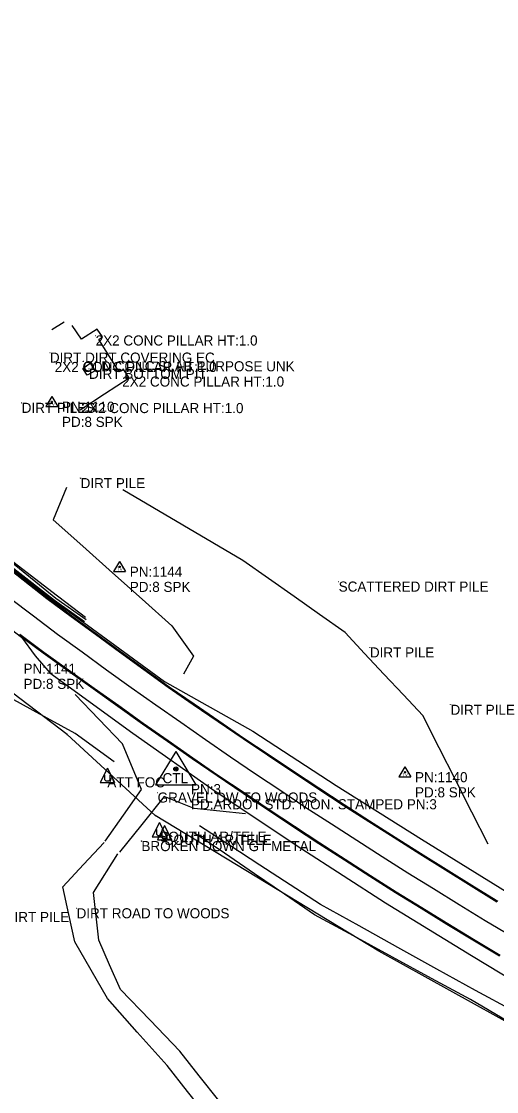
# Model space of a CAD drawing. Extents: x 878399 to 889864, y 1564003 to 1567413.
# Drawn here: x 885279 to 885515, y 1564809 to 1565340 of the extents above; entities that cross this region are included whole.
import ezdxf

# ---------------------------------------------------------------- set-up
doc = ezdxf.new("R2010")
doc.units = 0
for name, color, linetype in [('S_DITCHLINE', 7, 'Continuous'), ('S_DRIVEWAY', 7, 'Continuous'), ('S_EDGE_CONCRETE', 7, 'Continuous'), ('S_EDGE_PAVEMENT', 7, 'Continuous'), ('S_FIBER_OPTIC_CABLE', 7, 'Continuous'), ('S_GRAVEL_ROAD', 7, 'Continuous'), ('S_MSC_PT_SYM', 7, 'Continuous'), ('S_PAVEMENT_CROWN', 7, 'Continuous'), ('S_PRIMARY_CTL', 7, 'Continuous'), ('S_PRIMARY_CTL_ANNOT', 7, 'Continuous'), ('S_SECONDARY_CTL', 7, 'Continuous'), ('S_SECONDARY_CTL_ANNOT', 7, 'Continuous'), ('S_SHOULDER', 7, 'Continuous'), ('S_SURVEY_TEXT_ANNOT', 7, 'Continuous'), ('S_TRAILS', 7, 'Continuous'), ('S_UTILITY_POLE', 7, 'Continuous'), ('S_UTILITY_POLE_ANNOT', 7, 'Continuous'), ('S_UTL_PT_SYM', 7, 'Continuous')]:
    doc.layers.add(name, color=color, linetype=linetype)

msp = doc.modelspace()

# ---------------------------------------------------------------- linework, layer by layer
at = {"layer": 'S_DITCHLINE'}
for points in [[(885310.72, 1565044.3), (885294.14, 1565056.98), (885277.55, 1565069.67), (885260.97, 1565082.35), (885244.38, 1565095.03), (885226.71, 1565109.43), (885209.03, 1565123.82), (885191.36, 1565138.22), (885173.68, 1565152.61), (885155.49, 1565168.05), (885137.3, 1565183.48), (885119.12, 1565198.92), (885100.93, 1565214.35), (885083.52, 1565229.28), (885066.12, 1565244.2), (885048.72, 1565259.13), (885031.31, 1565274.06), (885014.49, 1565288.54), (884997.67, 1565303.02), (884980.86, 1565317.5), (884964.04, 1565331.98), (884961.88, 1565334.22), (884945.54, 1565347.97)], [(885324.96, 1564972.8), (885305.68, 1564986.74), (885284.83, 1564998.14), (885263.97, 1565009.54)], [(885523.05, 1564849.11), (885504.1, 1564859.3), (885484.87, 1564869.98), (885465.64, 1564880.65), (885446.41, 1564891.33), (885427.18, 1564902.01), (885412.2, 1564911.77), (885397.23, 1564921.52), (885382.25, 1564931.27), (885367.27, 1564941.03)], [(885520.12, 1564844.02), (885501.51, 1564854.81), (885482.2, 1564865.34), (885462.88, 1564875.86), (885443.57, 1564886.39), (885424.25, 1564896.92), (885409.36, 1564907.08), (885394.48, 1564917.24), (885379.59, 1564927.4), (885364.7, 1564937.57)]]:
    msp.add_lwpolyline(points, dxfattribs=at)
at = {"layer": 'S_DRIVEWAY'}
for points in [[(885320.58, 1564933.43), (885329.54, 1564946.24), (885338.49, 1564959.06), (885329.06, 1564981.63), (885317.32, 1564993.83), (885305.58, 1565006.04)], [(885390.06, 1564947), (885377.35, 1564948.3), (885364.65, 1564949.59), (885349.83, 1564955.51), (885338.76, 1564941.71), (885327.69, 1564927.92)]]:
    msp.add_lwpolyline(points, dxfattribs=at)
at = {"layer": 'S_EDGE_CONCRETE'}
for points in [[(884706.6, 1565551.45), (884725.44, 1565537.13), (884744.17, 1565521.12), (884782.46, 1565488.91), (884820.33, 1565456.29), (884857.4, 1565422.83), (884893.19, 1565391.5), (884931.44, 1565358.94), (884969.96, 1565327.51), (885007.93, 1565294.95), (885045.65, 1565262.19), (885083.76, 1565229.98), (885121.86, 1565197.67), (885159.74, 1565165.3), (885198.19, 1565133.4), (885236.59, 1565102.25), (885296.12, 1565053.84), (885311.12, 1565043.35)], [(884705.4, 1565550.04), (884723.26, 1565534.58), (884742.1, 1565518.69), (884780.16, 1565486.23), (884818.14, 1565453.73), (884855.98, 1565421.17), (884892.08, 1565390.2), (884930.32, 1565357.68), (884968.08, 1565325.3), (885005.99, 1565292.69), (885044.06, 1565260.33), (885082.07, 1565227.99), (885120, 1565195.47), (885157.99, 1565163.2), (885196.4, 1565131.24), (885234.81, 1565099.94), (885295.36, 1565052.86), (885310.26, 1565042.23)], [(885300.18, 1565190.78), (885293.99, 1565186.85)], [(885308.09, 1565147.19), (885320.22, 1565155.16), (885332.35, 1565163.12), (885329.79, 1565167.13), (885327.42, 1565166.07), (885317.29, 1565182.15), (885319.12, 1565183.47), (885316.62, 1565187.29), (885308.77, 1565182.26), (885304.13, 1565189.13)]]:
    msp.add_lwpolyline(points, dxfattribs=at)
msp.add_lwpolyline([(885311.59, 1565164.36), (885309.49, 1565167.78), (885313.01, 1565170.34), (885315.49, 1565166.6)], close=True, dxfattribs=at)
at = {"layer": 'S_EDGE_PAVEMENT'}
for points in [[(885267.94, 1565072.17), (885279.79, 1565062.98), (885291.64, 1565053.78), (885303.66, 1565044.82), (885315.76, 1565035.95), (885327.54, 1565027.32), (885339.64, 1565018.45), (885351.8, 1565009.67), (885364.17, 1565001.19), (885376.54, 1564992.7), (885388.91, 1564984.21), (885400.99, 1564976.14), (885413.48, 1564967.83), (885425.97, 1564959.51), (885425.97, 1564959.51), (885425.97, 1564959.51), (885438.54, 1564951.32), (885451.17, 1564943.22), (885463.8, 1564935.13), (885463.8, 1564935.13), (885476.45, 1564927.08), (885489.2, 1564919.17), (885501.96, 1564911.27), (885514.71, 1564903.36)], [(885268.33, 1565072.47), (885280.18, 1565063.28), (885292.03, 1565054.09), (885304.05, 1565045.13), (885316.14, 1565036.25), (885327.93, 1565027.62), (885340.03, 1565018.76), (885352.19, 1565009.98), (885364.55, 1565001.49), (885376.92, 1564993.01), (885389.29, 1564984.52), (885401.37, 1564976.45), (885413.86, 1564968.13), (885426.35, 1564959.82), (885426.35, 1564959.82), (885426.35, 1564959.82), (885438.92, 1564951.63), (885451.55, 1564943.53), (885464.18, 1564935.44), (885464.18, 1564935.44), (885476.83, 1564927.39), (885489.58, 1564919.48), (885502.33, 1564911.58), (885515.08, 1564903.67)], [(885277.76, 1565035.77), (885289.77, 1565026.8), (885301.96, 1565018.04), (885314.61, 1565009.01), (885326.82, 1565000.29), (885339.03, 1564991.58), (885351.34, 1564983.01), (885363.65, 1564974.45), (885375.97, 1564965.88), (885388.95, 1564957.15), (885401.44, 1564948.84), (885401.44, 1564948.84), (885401.44, 1564948.84), (885413.93, 1564940.53), (885426.48, 1564932.3), (885439.1, 1564924.19), (885451.72, 1564916.08), (885464.35, 1564907.99), (885477.14, 1564900.15), (885477.14, 1564900.15), (885489.93, 1564892.31), (885502.72, 1564884.47), (885516, 1564876.5)], [(885278.15, 1565036.08), (885290.16, 1565027.1), (885302.35, 1565018.35), (885315, 1565009.31), (885327.2, 1565000.59), (885339.42, 1564991.89), (885351.73, 1564983.32), (885364.04, 1564974.75), (885376.35, 1564966.19), (885389.33, 1564957.46), (885401.82, 1564949.15), (885401.82, 1564949.15), (885401.82, 1564949.15), (885414.32, 1564940.84), (885426.86, 1564932.61), (885439.48, 1564924.5), (885452.1, 1564916.39), (885464.73, 1564908.3), (885477.52, 1564900.46), (885477.52, 1564900.46), (885490.31, 1564892.62), (885503.1, 1564884.78), (885516.37, 1564876.81)]]:
    msp.add_lwpolyline(points, dxfattribs=at)
at = {"layer": 'S_FIBER_OPTIC_CABLE'}
for p, q in [((885301.6, 1564986.24), (885250.1, 1565025.48)), ((885345.35, 1564946.19), (885301.6, 1564986.24)), ((885456.16, 1564878.83), (885345.35, 1564946.19)), ((885547.89, 1564828.01), (885456.16, 1564878.83))]:
    msp.add_line(p, q, dxfattribs=at)
at = {"layer": 'S_GRAVEL_ROAD'}
for points in [[(885301.36, 1565108.82), (885294.78, 1565092.74), (885309.46, 1565079.6), (885324.13, 1565066.46), (885338.8, 1565053.32), (885353.48, 1565040.18), (885364.23, 1565025.11), (885359.33, 1565016.16)], [(885510.35, 1564931.82), (885502.25, 1564947.77), (885494.14, 1564963.73), (885486.04, 1564979.68), (885477.93, 1564995.63), (885468.3, 1565005.92), (885458.67, 1565016.22), (885449.05, 1565026.51), (885439.42, 1565036.81), (885426.77, 1565045.76), (885414.12, 1565054.71), (885401.47, 1565063.67), (885388.81, 1565072.62), (885373.94, 1565081.37), (885359.06, 1565090.12), (885344.18, 1565098.86), (885329.3, 1565107.61)]]:
    msp.add_lwpolyline(points, dxfattribs=at)
at = {"layer": 'S_MSC_PT_SYM'}
for points in [[(885315.78, 1565184.13), (885315.78, 1565184.18), (885315.78, 1565184.13), (885315.73, 1565184.13), (885315.78, 1565184.13), (885315.78, 1565184.08), (885315.78, 1565184.13), (885315.83, 1565184.13)], [(885293.11, 1565175.64), (885293.11, 1565175.69), (885293.11, 1565175.64), (885293.06, 1565175.64), (885293.11, 1565175.64), (885293.11, 1565175.59), (885293.11, 1565175.64), (885293.16, 1565175.64)], [(885295.49, 1565170.99), (885295.49, 1565171.04), (885295.49, 1565170.99), (885295.44, 1565170.99), (885295.49, 1565170.99), (885295.49, 1565170.94), (885295.49, 1565170.99), (885295.54, 1565170.99)], [(885309.66, 1565171.34), (885309.66, 1565171.39), (885309.66, 1565171.34), (885309.61, 1565171.34), (885309.66, 1565171.34), (885309.66, 1565171.29), (885309.66, 1565171.34), (885309.71, 1565171.34)], [(885312.51, 1565167.6), (885312.51, 1565167.65), (885312.51, 1565167.6), (885312.46, 1565167.6), (885312.51, 1565167.6), (885312.51, 1565167.55), (885312.51, 1565167.6), (885312.56, 1565167.6)], [(885328.95, 1565163.76), (885328.95, 1565163.81), (885328.95, 1565163.76), (885328.9, 1565163.76), (885328.95, 1565163.76), (885328.95, 1565163.71), (885328.95, 1565163.76), (885329, 1565163.76)], [(885279.13, 1565150.74), (885279.13, 1565150.79), (885279.13, 1565150.74), (885279.08, 1565150.74), (885279.13, 1565150.74), (885279.13, 1565150.69), (885279.13, 1565150.74), (885279.18, 1565150.74)], [(885308.79, 1565150.62), (885308.79, 1565150.67), (885308.79, 1565150.62), (885308.74, 1565150.62), (885308.79, 1565150.62), (885308.79, 1565150.57), (885308.79, 1565150.62), (885308.84, 1565150.62)], [(885308.34, 1565113.41), (885308.34, 1565113.46), (885308.34, 1565113.41), (885308.29, 1565113.41), (885308.34, 1565113.41), (885308.34, 1565113.36), (885308.34, 1565113.41), (885308.39, 1565113.41)], [(885436.24, 1565062.11), (885436.24, 1565062.16), (885436.24, 1565062.11), (885436.19, 1565062.11), (885436.24, 1565062.11), (885436.24, 1565062.06), (885436.24, 1565062.11), (885436.29, 1565062.11)], [(885451.72, 1565029.46), (885451.72, 1565029.51), (885451.72, 1565029.46), (885451.67, 1565029.46), (885451.72, 1565029.46), (885451.72, 1565029.41), (885451.72, 1565029.46), (885451.77, 1565029.46)], [(885491.67, 1565001.03), (885491.67, 1565001.08), (885491.67, 1565001.03), (885491.62, 1565001.03), (885491.67, 1565001.03), (885491.67, 1565000.98), (885491.67, 1565001.03), (885491.72, 1565001.03)], [(885346.5, 1564957.53), (885346.5, 1564957.58), (885346.5, 1564957.53), (885346.45, 1564957.53), (885346.5, 1564957.53), (885346.5, 1564957.48), (885346.5, 1564957.53), (885346.55, 1564957.53)], [(885338.48, 1564933.44), (885338.48, 1564933.49), (885338.48, 1564933.44), (885338.43, 1564933.44), (885338.48, 1564933.44), (885338.48, 1564933.39), (885338.48, 1564933.44), (885338.53, 1564933.44)], [(885306.33, 1564900.15), (885306.33, 1564900.2), (885306.33, 1564900.15), (885306.28, 1564900.15), (885306.33, 1564900.15), (885306.33, 1564900.1), (885306.33, 1564900.15), (885306.38, 1564900.15)]]:
    msp.add_lwpolyline(points, dxfattribs=at)
at = {"layer": 'S_PAVEMENT_CROWN'}
msp.add_lwpolyline([(885272.99, 1565054.15), (885284.94, 1565045.08), (885296.92, 1565036.06), (885309.05, 1565027.24), (885321.24, 1565018.39), (885333.37, 1565009.57), (885345.64, 1565000.94), (885357.94, 1564992.36), (885370.24, 1564983.77), (885382.61, 1564975.28), (885395.1, 1564966.85), (885407.54, 1564958.46), (885420.01, 1564950.12), (885432.62, 1564941.99), (885445.23, 1564933.86), (885457.83, 1564925.73), (885470.55, 1564917.77), (885483.29, 1564909.85), (885496.03, 1564901.93), (885508.85, 1564894.12), (885521.79, 1564886.41)], dxfattribs=at)
at = {"layer": 'S_PRIMARY_CTL'}
for p, q in [((885355.55, 1564977.89), (885345.51, 1564961.38)), ((885355.55, 1564977.89), (885365.37, 1564961.38)), ((885345.51, 1564961.38), (885365.37, 1564961.38))]:
    msp.add_line(p, q, dxfattribs=at)
for radius in [1.04, 0.609, 0.344]:
    msp.add_circle((885355.55, 1564969.19), radius, dxfattribs=at)
at = {"layer": 'S_SECONDARY_CTL'}
for p, q in [((885294.09, 1565153.89), (885291.08, 1565148.93)), ((885294.09, 1565153.89), (885297.04, 1565148.93)), ((885291.08, 1565148.93), (885297.04, 1565148.93)), ((885327.69, 1565072.07), (885324.68, 1565067.12)), ((885327.69, 1565072.07), (885330.64, 1565067.12)), ((885324.68, 1565067.12), (885330.64, 1565067.12)), ((885469.09, 1564970.22), (885466.08, 1564965.26)), ((885469.09, 1564970.22), (885472.04, 1564965.26)), ((885466.08, 1564965.26), (885472.04, 1564965.26))]:
    msp.add_line(p, q, dxfattribs=at)
for centre, radius in [((885294.09, 1565151.27), 0.311), ((885294.09, 1565151.27), 0.183), ((885294.09, 1565151.27), 0.103), ((885327.69, 1565069.46), 0.311), ((885327.69, 1565069.46), 0.183), ((885327.69, 1565069.46), 0.103), ((885469.09, 1564967.61), 0.311), ((885469.09, 1564967.61), 0.183), ((885469.09, 1564967.61), 0.103)]:
    msp.add_circle(centre, radius, dxfattribs=at)
at = {"layer": 'S_SHOULDER'}
for points in [[(884891.75, 1565389.81), (884929.91, 1565357.22), (884967.7, 1565324.86), (885005.68, 1565292.33), (885043.8, 1565260.03), (885081.58, 1565227.41), (885119.6, 1565195.01), (885157.6, 1565162.73), (885196.01, 1565130.77), (885234.52, 1565099.56), (885295.12, 1565052.54), (885309.99, 1565041.88), (885349.92, 1565012.53), (885393.73, 1564987.91), (885434.98, 1564961), (885477.34, 1564934.42), (885519.82, 1564908.04)], [(884883.27, 1565365.1), (884921.11, 1565332.91), (884959.44, 1565300.44), (884997.33, 1565267.94), (885035.39, 1565235.57), (885073.41, 1565203.07), (885111.37, 1565170.59), (885149.81, 1565138.45), (885188.01, 1565106.23), (885227.26, 1565074.48), (885266.77, 1565043.86), (885279.08, 1565034.55), (885285.74, 1565025.23), (885293.12, 1565016.93), (885334.15, 1564986.97), (885375, 1564958.16), (885417.46, 1564929.91), (885459.52, 1564902.88), (885502.12, 1564876.69), (885545.5, 1564850.36)]]:
    msp.add_lwpolyline(points, dxfattribs=at)
at = {"layer": 'S_TRAILS'}
for points in [[(885416.6, 1564707.68), (885409.49, 1564727.82), (885402.37, 1564747.96), (885394.65, 1564760.08), (885386.93, 1564772.21), (885379.21, 1564784.33), (885371.49, 1564796.45), (885361.33, 1564809.27), (885351.18, 1564822.09), (885336.4, 1564838.75), (885321.63, 1564855.4), (885313.57, 1564869.43), (885305.5, 1564883.46), (885302.5, 1564897.11), (885299.51, 1564910.76), (885309.8, 1564921.76), (885320.09, 1564932.75)], [(885424.31, 1564719.24), (885416.48, 1564737.66), (885408.65, 1564756.08), (885400.7, 1564768.27), (885392.75, 1564780.47), (885384.8, 1564792.66), (885376.85, 1564804.86), (885367.15, 1564817.1), (885357.45, 1564829.35), (885342.74, 1564844.59), (885328.03, 1564859.83), (885322.68, 1564872.07), (885317.34, 1564884.31), (885314.66, 1564908), (885326.86, 1564927.19)]]:
    msp.add_lwpolyline(points, dxfattribs=at)
at = {"layer": 'S_UTILITY_POLE'}
for p, q in [((885321.58, 1564969.58), (885318.05, 1564962.49)), ((885321.58, 1564969.58), (885325.06, 1564962.49)), ((885318.05, 1564962.49), (885325.06, 1564962.49)), ((885320.38, 1564963.73), (885320.38, 1564966.17)), ((885321, 1564963.07), (885320.38, 1564963.73)), ((885322.2, 1564963.07), (885321, 1564963.07)), ((885322.74, 1564963.73), (885322.2, 1564963.07)), ((885322.74, 1564966.17), (885322.74, 1564963.73)), ((885347.4, 1564942.62), (885343.87, 1564935.53)), ((885349.91, 1564941.1), (885346.38, 1564934.01)), ((885347.4, 1564942.62), (885350.88, 1564935.53)), ((885349.91, 1564941.1), (885353.39, 1564934.01)), ((885343.87, 1564935.53), (885350.88, 1564935.53)), ((885346.19, 1564936.77), (885346.19, 1564939.21)), ((885346.81, 1564936.11), (885346.19, 1564936.77)), ((885348.02, 1564936.11), (885346.81, 1564936.11)), ((885348.56, 1564936.77), (885348.02, 1564936.11)), ((885348.56, 1564939.21), (885348.56, 1564936.77)), ((885348.71, 1564935.25), (885348.71, 1564937.69)), ((885351.07, 1564937.69), (885351.07, 1564935.25)), ((885346.38, 1564934.01), (885353.39, 1564934.01)), ((885349.33, 1564934.59), (885348.71, 1564935.25)), ((885350.53, 1564934.59), (885349.33, 1564934.59)), ((885351.07, 1564935.25), (885350.53, 1564934.59))]:
    msp.add_line(p, q, dxfattribs=at)
at = {"layer": 'S_UTL_PT_SYM'}
for points in [[(885301.6, 1564986.24), (885301.6, 1564986.29), (885301.6, 1564986.24), (885301.55, 1564986.24), (885301.6, 1564986.24), (885301.6, 1564986.19), (885301.6, 1564986.24), (885301.65, 1564986.24)], [(885345.35, 1564946.19), (885345.35, 1564946.24), (885345.35, 1564946.19), (885345.3, 1564946.19), (885345.35, 1564946.19), (885345.35, 1564946.14), (885345.35, 1564946.19), (885345.4, 1564946.19)], [(885456.16, 1564878.83), (885456.16, 1564878.88), (885456.16, 1564878.83), (885456.11, 1564878.83), (885456.16, 1564878.83), (885456.16, 1564878.78), (885456.16, 1564878.83), (885456.21, 1564878.83)]]:
    msp.add_lwpolyline(points, dxfattribs=at)

# ---------------------------------------------------------------- texts
at = {"layer": 'S_PRIMARY_CTL'}
msp.add_text('CTL', height=5, rotation=360, dxfattribs=at).set_placement((885348.96, 1564962.12))
at = {"layer": 'S_PRIMARY_CTL_ANNOT'}
for s, p in [('PN:3', (885363.05, 1564956.69)), ('PD:ARDOT STD. MON. STAMPED PN:3', (885363.05, 1564949.19))]:
    msp.add_text(s, height=5, dxfattribs=at).set_placement(p)
at = {"layer": 'S_SECONDARY_CTL'}
for p in [(885292.88, 1565149.26), (885326.48, 1565067.45), (885467.88, 1564965.59)]:
    msp.add_text('TV', height=1.5, rotation=360, dxfattribs=at).set_placement(p)
at = {"layer": 'S_SECONDARY_CTL_ANNOT'}
for s, p in [('PN:1110', (885299.09, 1565146.28)), ('PD:8 SPK', (885299.09, 1565138.78)), ('PN:1144', (885332.69, 1565064.46)), ('PD:8 SPK', (885332.69, 1565056.96)), ('PN:1141', (885280.02, 1565016.38)), ('PD:8 SPK', (885280.02, 1565008.88)), ('PN:1140', (885474.09, 1564962.61)), ('PD:8 SPK', (885474.09, 1564955.11))]:
    msp.add_text(s, height=5, dxfattribs=at).set_placement(p)
at = {"layer": 'S_SURVEY_TEXT_ANNOT'}
for s, p in [('2X2 CONC PILLAR HT:1.0', (885315.78, 1565179.13)), ('DIRT DIRT COVERING EC', (885293.11, 1565170.64)), ('2X2 CONC PILLAR HT:1.0', (885295.49, 1565165.99)), ('OLD CONC SLAB PURPOSE UNK', (885309.66, 1565166.34)), ('DIRT BOTTOM PIT', (885312.51, 1565162.6)), ('2X2 CONC PILLAR HT:1.0', (885328.95, 1565158.76)), ('DIRT PILES', (885279.13, 1565145.74)), ('2X2 CONC PILLAR HT:1.0', (885308.79, 1565145.62)), ('DIRT PILE', (885308.34, 1565108.41)), ('SCATTERED DIRT PILE', (885436.24, 1565057.11)), ('DIRT PILE', (885451.72, 1565024.46)), ('DIRT PILE', (885491.67, 1564996.03)), ('GRAVEL DW TO WOODS', (885346.5, 1564952.53)), ('BROKEN DOWN GT METAL', (885338.48, 1564928.44)), ('SCATTERED DIRT PILE', (885228.4, 1564893.27)), ('DIRT ROAD TO WOODS', (885306.33, 1564895.15))]:
    msp.add_text(s, height=5, dxfattribs=at).set_placement(p)
at = {"layer": 'S_UTILITY_POLE_ANNOT'}
for s, p in [('ATT FOC', (885321.58, 1564960.05)), ('SOUTH AR/TELE', (885347.4, 1564933.09)), ('SOUTH AR/TELE', (885349.91, 1564931.56))]:
    msp.add_text(s, height=5, dxfattribs=at).set_placement(p)

doc.saveas('drawing.dxf')
